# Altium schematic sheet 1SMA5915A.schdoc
size 127 x 101 mm
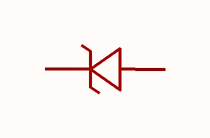
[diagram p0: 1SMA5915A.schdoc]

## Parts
D?  1sma5915a  [SMA_L4.3-W2.6-LS5.2-RD]  (value not drawn)

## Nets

Not connected (* = marked no-connect by the designer): D? 1(K) 2(A)

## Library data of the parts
D? = 1sma5915a: 二极管配置:1个独立式;稳压值(标称值):3.9V;稳压值(范围):3.7V~4.1V;耗散功率(Pd):1.5W;; Manufacturer: CJ(江苏长电/长晶); AddInBom: yes; ModelId: e3551acb3c5a4975a5e9d36087fe1fa2; ModelTransform: 185.039,102.362,0,0,0,0,0,0,0; Diode Configuration: 1个独立式; Zener Voltage(Nom): 3.9V; Reverse Leakage Current (Ir): 12.5uA@1V; Pd - Power Dissipation: 1.5W; Impedance(Zzt): 7.5Ω; Impedance(Zzk): 500Ω; Operating Junction Temperature Range: -55℃~+150℃; Tolerance: ±5%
